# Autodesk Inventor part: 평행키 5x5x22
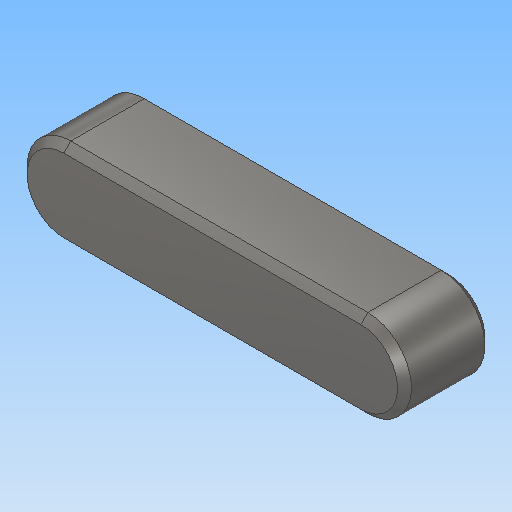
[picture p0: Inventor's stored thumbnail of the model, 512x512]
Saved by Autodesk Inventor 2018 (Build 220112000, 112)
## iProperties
Created: 2024-09
Part Number: 평행키 5x5x22
Material: 강철, 연강
Description: 키 및 해당 키홈
Document SubType Name: Modeling
Designer: home
Density: 7.85 g/cm^3
Appearance: 기본값
Author: jhkim
Sending System: Autodesk Inventor 2025
Preprocessor: ST-DEVELOPER v20
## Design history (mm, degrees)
feature "Solid1"
node "솔리드1"
